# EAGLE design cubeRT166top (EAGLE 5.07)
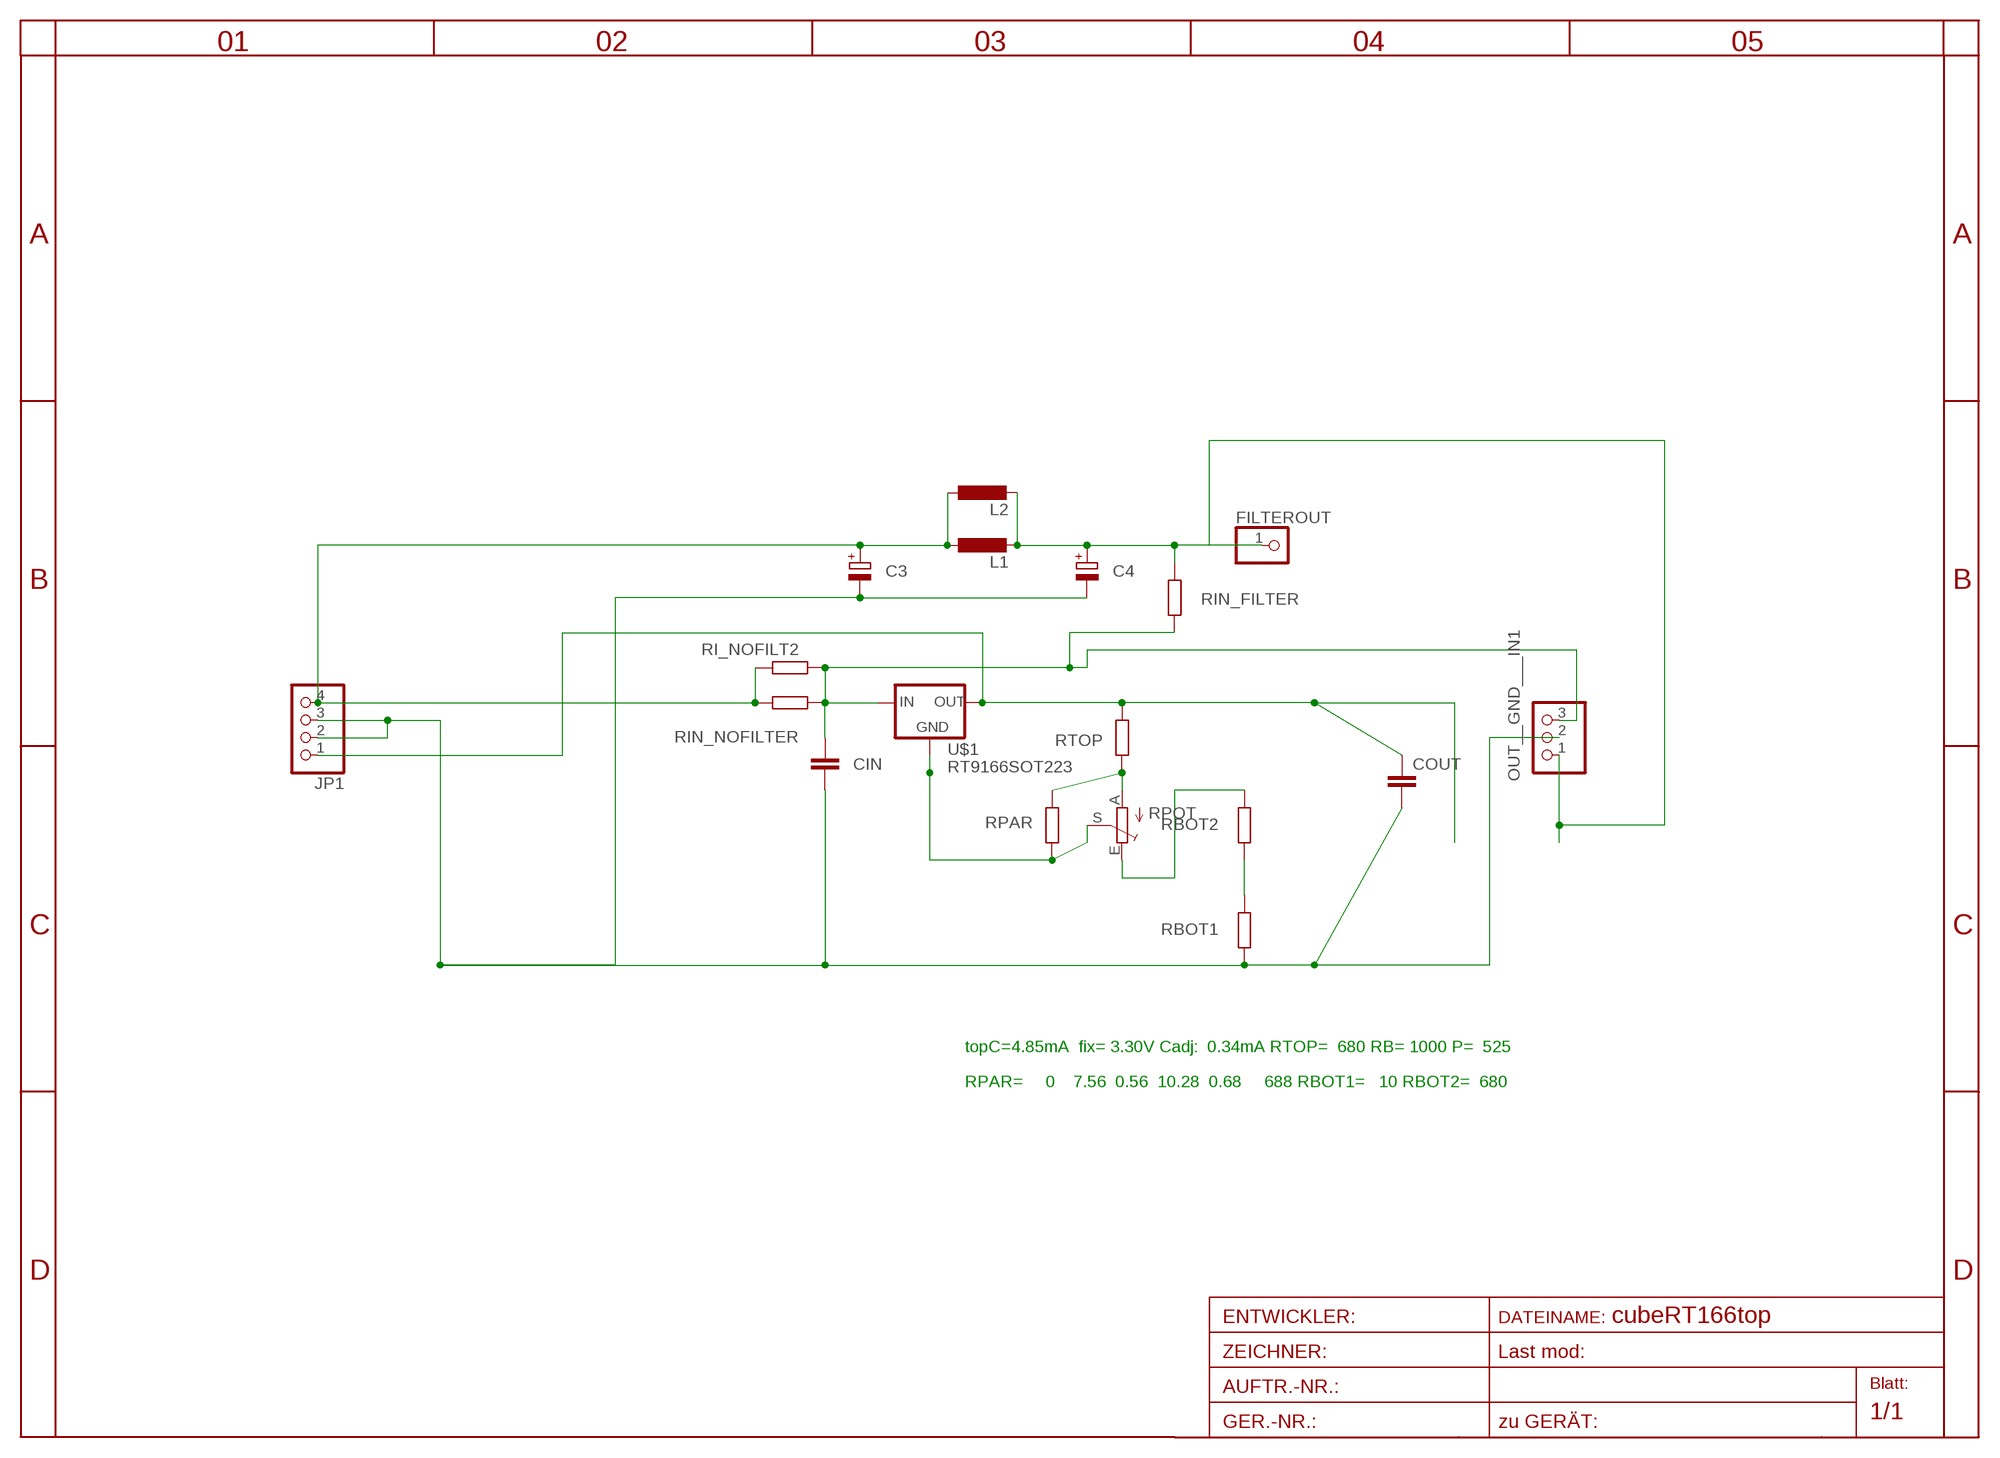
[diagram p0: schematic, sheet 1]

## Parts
C3  CPOL-EUE  [PANASONIC_E]
C4  CPOL-EUE  [PANASONIC_E]
CIN  C-EUC1206  [C1206]
COUT  C-EUC1206  [C1206]
FILTEROUT  PINHD-1X11X0.4  [1X01]
JP1  PINHD-1X4  [1X04]
L1  L-EUPIS2816  [PIS2816]
L2  L-EUOPEN  [OPEN5]
OUT__GND___IN1  PINHD-1X3  [1X03]
RBOT1  R-EU_R0805  [R0805]
RBOT2  R-EU_R0805  [R0805]
RI_NOFILT2  R-EU_R0805  [R0805]
RIN_FILTER  R-EU_R0805  [R0805]
RIN_NOFILTER  R-EU_R0805  [R0805]
RPAR  R-EU_R0805  [R0805]
RPOT  TRIM_EU-RAND160  [RANDL]
RTOP  R-EU_R0805  [R0805]
U$1  RT9166SOT223  [SOT223]

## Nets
ADJ: RPAR.1 RPOT.S U$1.2(GND) U$1.4(GND1)
GND: C3.- C4.- CIN.2 COUT.2 JP1.2 JP1.3 OUT__GND___IN1.2 RBOT1.1
IN: CIN.1 OUT__GND___IN1.3 RI_NOFILT2.1 RIN_FILTER.2 RIN_NOFILTER.1 U$1.3(IN)
N$1: C3.+ JP1.4 L1.1 L2.1 RI_NOFILT2.2 RIN_NOFILTER.2
N$2: RPAR.2 RPOT.A RTOP.1
N$3: C4.+ FILTEROUT.1 L1.2 L2.2 OUT__GND___IN1.1 RIN_FILTER.1
N$4: RBOT2.2 RPOT.E
N$5: RBOT1.2 RBOT2.1
OUT: COUT.1 JP1.1 RTOP.2 U$1.1(OUT)

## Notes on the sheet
- topC=4.85mA  fix= 3.30V Cadj:  0.34mA RTOP=  680 RB= 1000 P=  525
- RPAR=     0    7.56  0.56  10.28  0.68     688 RBOT1=   10 RBOT2=  680

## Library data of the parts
C3 C4 = rcl:CPOL-EU: POLARIZED CAPACITOR, European symbol
CIN COUT = rcl:C-EU: CAPACITOR, European symbol
FILTEROUT = pinhead:PINHD-1X1: PIN HEADER
JP1 = pinhead:PINHD-1X4: PIN HEADER
L1 L2 = rcl:L-EU: INDUCTOR, European symbol
OUT__GND___IN1 = pinhead:PINHD-1X3: PIN HEADER
RBOT1 RBOT2 RI_NOFILT2 RIN_FILTER RIN_NOFILTER RPAR RTOP = rcl:R-EU_: RESISTOR, European symbol
RPOT = pot:TRIM_EU-: POTENTIOMETER
U$1 = v-reg:RT9166

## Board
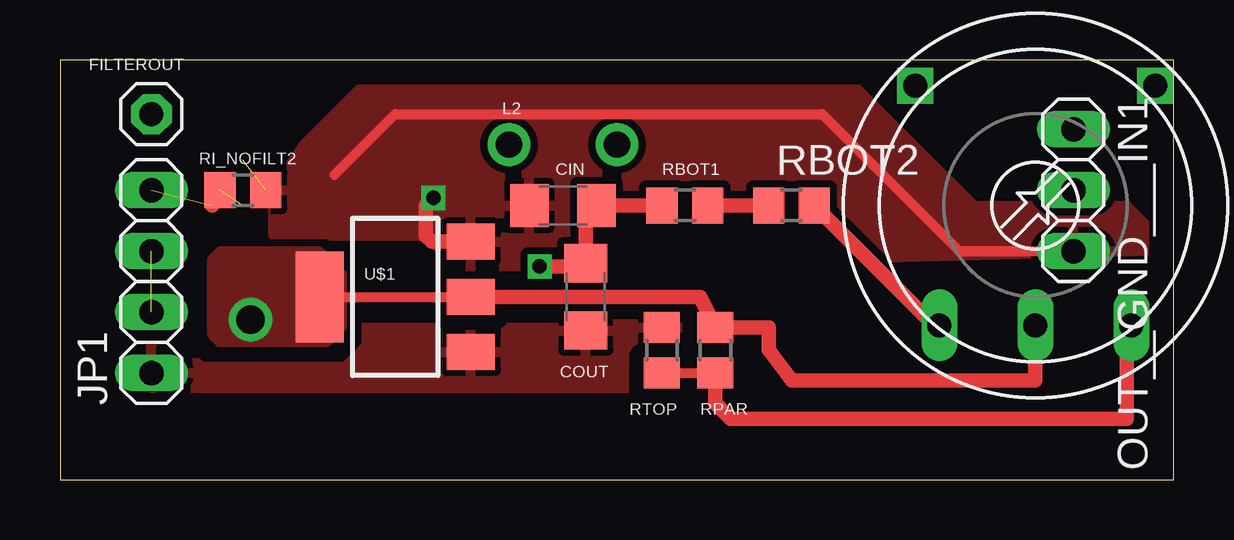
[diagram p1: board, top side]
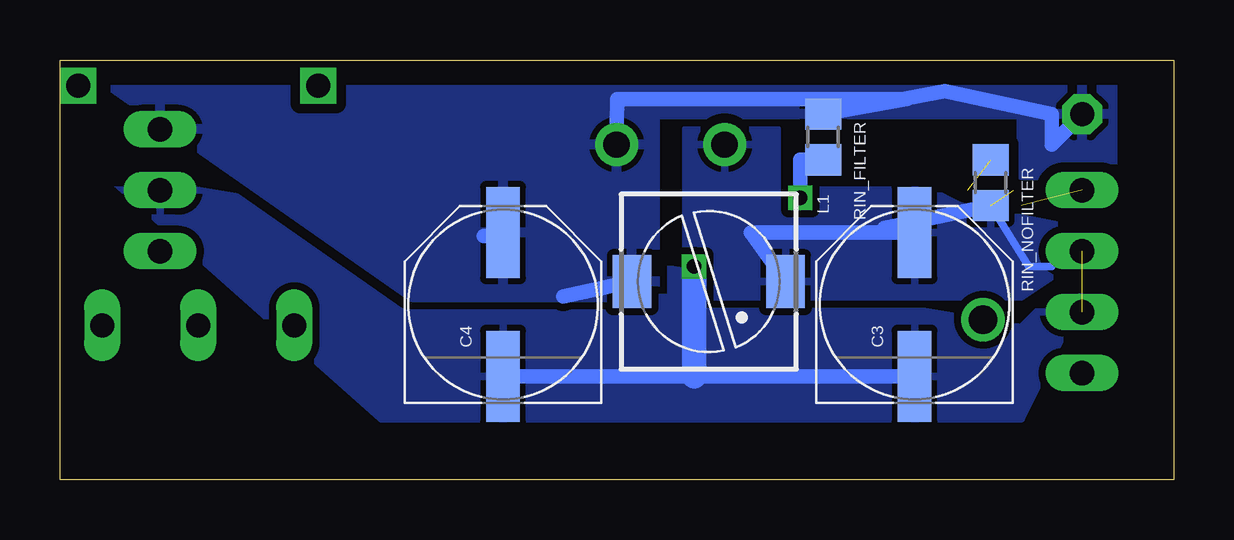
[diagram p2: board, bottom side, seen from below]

Size 46.4 x 17.5 mm. Coordinates in mm from the lower left corner, seen from the top.
Outline: 0,0 46.4,0 46.4,17.5 0,17.5 0,0
Copper layers (1*16): Top 0.035mm / dielectric 1.5mm / Bottom 0.035mm
Design rules "default *": minimum track width 10mil, minimum drill 20mil, track to track 8mil, track to pad 8mil, pad to pad 8mil, via to via 8mil, smd to smd 8mil, copper to edge 40mil, drill to drill 8mil, minimum pad ring 1mil, minimum via ring 8mil, stop-mask expansion 4mil, vias tented up to drill 0mil, thermal gap 10mil

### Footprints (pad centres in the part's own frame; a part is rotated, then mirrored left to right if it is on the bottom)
PANASONIC_E = smd 3.8 x 1.4: + 3,0; - -3,0
C1206 = smd 1.6 x 1.8: 1 -1.4,0; 2 1.4,0
1X01 = drill 1 pad 1.676 octagon: 1 0,0
1X04 = drill 1.016 long: 1 -3.81,0; 2 -1.27,0; 3 1.27,0; 4 3.81,0
PIS2816 = smd 2.2 x 1.6: 1 0,3.2; 2 0,-3.2
OPEN5 = drill 1.1 pad 1.778 round: 1 -2.25,0; 2 2.25,0
1X03 = drill 1.016 long: 1 -2.54,0; 2 0,0; 3 2.54,0
R0805 = smd 1.3 x 1.5: 1 -0.95,0; 2 0.95,0
RANDL = drill 1 long: A -4,5; E 4,5; S 0,5 | drill 1 square: P$1 -5,-5; P$2 5,-5
SOT223 = smd 1.5 x 2: 1 -2.3,-3.15; 2 0,-3.15; 3 2.3,-3.15 | smd 3.8 x 2: 4 0,3.15

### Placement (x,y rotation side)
C3  10.79,7.3 90 bottom
C4  27.94,7.3 90 bottom
CIN  20.95,11.43 0 top
COUT  21.91,7.62 90 top
FILTEROUT  3.81,15.24 0 top
JP1  3.81,8.26 90 top
L1  19.37,8.26 270 bottom
L2  20.95,13.97 0 top
OUT__GND___IN1  42.23,12.06 270 top
RBOT1  26.04,11.43 0 top
RBOT2  30.48,11.43 0 top
RI_NOFILT2  7.62,12.06 180 top
RIN_FILTER  14.61,14.29 270 bottom
RIN_NOFILTER  7.62,12.38 270 bottom
RPAR  27.3,5.4 270 top
RPOT  40.64,11.43 180 top
RTOP  25.08,5.4 90 top
U$1  13.97,7.62 90 top

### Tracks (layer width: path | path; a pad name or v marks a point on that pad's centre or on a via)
ADJ  (via drill 1.2)
  Top 0.406: U$1.4 U$1.2
  Top 0.61: U$1.2 26.67,7.62 RPAR.1 29.53,6.35 29.53,5.4 30.48,4.13 40.64,4.13 RPOT.S
  other vias: 7.94,6.67
  pour Top (no thermals): 6.35,6.03 6.35,9.21 6.67,9.53 10.79,9.53 11.75,8.57 11.75,6.35 11.11,5.71 6.67,5.71
GND  (via drill 0.6)  (1 unrouted)
  Top 0.406: 21.59,8.89 21.59,9.02 COUT.2 | 21.91,10.79 CIN.2
  Top 0.61: v19.98,8.89 21.59,8.89 | COUT.2 21.91,10.79 | CIN.2 RBOT1.1
  Bottom 0.61: C3.- 19.98,4.3 C4.-
  Bottom 1.016: 19.98,4.3 v19.98,8.89
  pour Bottom (isolate 0.305, rank 3): 3.81,7.62 5.08,7.62 6.35,6.35 44.45,12.7 33.02,2.54 6.35,2.54
IN  (via drill 0.6)  (1 unrouted)
  Top 0.406: OUT__GND___IN1.3 37.47,9.53 31.75,15.24 13.97,15.24 11.43,12.7
  Top 0.61: v15.56,11.75 15.24,11.43 15.24,10.16 15.48,9.92 U$1.3
  Bottom 0.61: RIN_FILTER.2 15.56,13.34 v15.56,11.75
  pour Top (isolate 0.305, rank 2): 45.72,9.53 20.32,8.89 16.51,8.89 15.24,10.16 8.89,10.16 8.89,12.06 10.16,13.97 12.7,16.51 33.02,16.51 38.1,11.43 44.45,11.43 45.72,10.16
N$1  (2 unrouted)
  Top 0.61: RI_NOFILT2.2 6.35,11.43
  Bottom 0.305: 5.08,8.89 6.03,8.89 RIN_NOFILTER.2
  Bottom 0.61: RIN_NOFILTER.2 12.06,10.48 C3.+ 17.61,10.3 L1.1
  pour Bottom (isolate 0.305, rank 2): 2.54,10.16 6.35,7.62 20.32,7.62 20.32,14.61 16.51,14.61 16.51,12.06 10.16,12.06 8.89,11.43
N$2
  Top 0.406: RTOP.1 RPAR.2
  Top 0.61: RPOT.A 44.45,6.24 44.45,2.54 27.94,2.54 27.3,3.17 RPAR.2
N$3
  Bottom 0.61: L1.2 25.43,7.64 | 28.75,10.16 27.94,10.16 | FILTEROUT.1 5.08,13.97 5.08,15.24 9.53,16.19 RIN_FILTER.1 11.12,15.88 23.18,15.88 23.2,14.89 L2.2
  pour Bottom (isolate 0.406): 2.54,16.51 44.45,16.51 31.75,7.62 21.59,7.62 21.59,15.24 6.35,15.24 6.35,12.7 2.54,12.7
N$4
  Top 0.61: RBOT2.2 36.43,6.43 RPOT.E
N$5
  Top 0.61: RBOT1.2 RBOT2.1
OUT
  pour Top (isolate 0.61, rank 3): 3.81,6.35 21.59,6.35 22.86,7.62 26.67,7.62 26.67,5.08 25.4,3.81 3.81,3.81

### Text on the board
tStop: MICHAEL5.net
bStop: MICHAEL5.net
